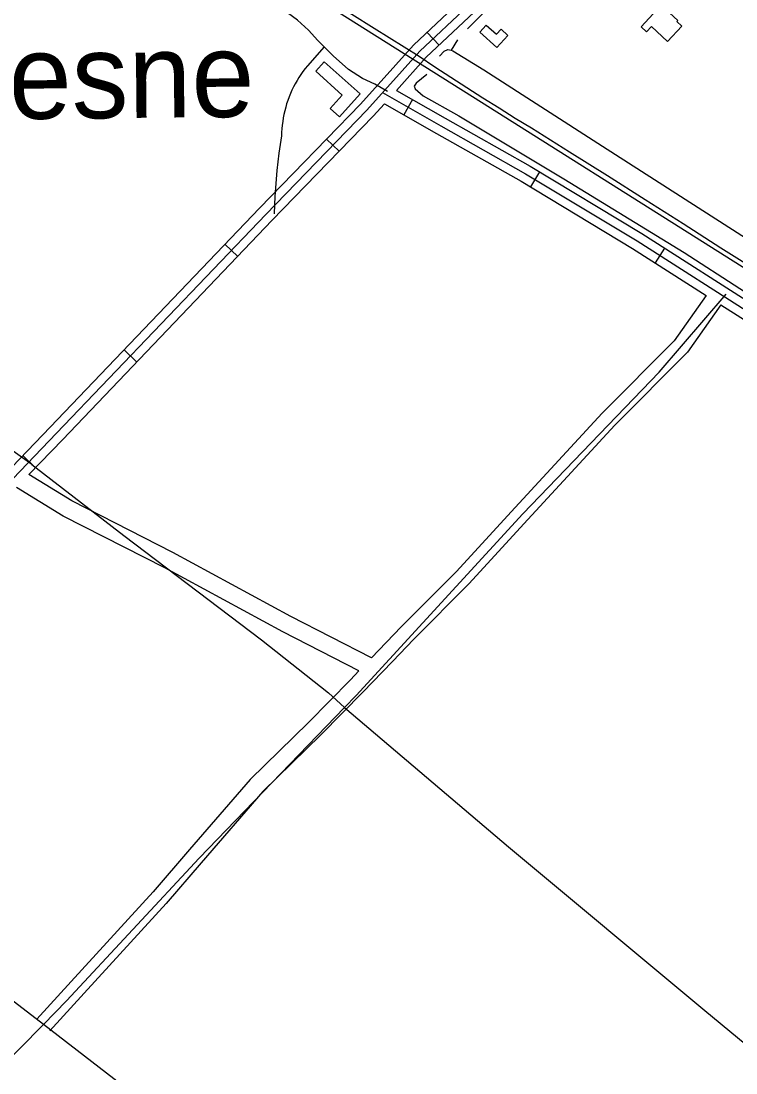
# Model space of a CAD drawing. Extents: x 3567028 to 3605064, y 510945 to 536587.
# Drawn here: x 3578608 to 3579831, y 524024 to 525823 of the extents above; entities that cross this region are included whole.
import ezdxf

# ---------------------------------------------------------------- set-up
doc = ezdxf.new("R2010")
doc.units = 0
for name, color, linetype in [('V-BLDG-OTLN', 7, 'Continuous'), ('V-DTCH-CNTR', 7, 'Continuous'), ('V-RAIL-TRAK', 7, 'Continuous'), ('V-ROAD-CNTR', 7, 'Continuous'), ('V-TOPO-GNAM-IDEN', 7, 'Continuous'), ('V-TOPO-SHOR', 7, 'Continuous')]:
    doc.layers.add(name, color=color, linetype=linetype)

msp = doc.modelspace()

# ---------------------------------------------------------------- linework, layer by layer
at = {"layer": 'V-BLDG-OTLN'}
for points in [[(3579668.3, 525812.8), (3579702.7, 525850.1), (3579731.4, 525823.6), (3579729.7, 525821.7), (3579737.9, 525814.2), (3579713.8, 525788), (3579686.3, 525813.4), (3579677.7, 525804.1)], [(3579440.6, 525798), (3579421.6, 525777.3), (3579392.7, 525803.9), (3579403.6, 525815.9), (3579420.8, 525800.1), (3579428.9, 525808.8)], [(3579126.4, 525752.9), (3579187.6, 525698.1), (3579152.4, 525658.8), (3579136.6, 525673), (3579157.3, 525696.1), (3579111.9, 525736.8)]]:
    msp.add_lwpolyline(points, close=True, dxfattribs=at)
at = {"layer": 'V-DTCH-CNTR'}
for points in [[(3579234.5, 525702), (3579213.1, 525714.8), (3579191.9, 525724.7), (3579167.8, 525740), (3579141.8, 525763), (3579126.3, 525778.7), (3579115.6, 525789.6), (3579099.3, 525807.1), (3579080.9, 525824), (3579063.6, 525836.8), (3578973.6, 525897.7), (3578789, 526012), (3578549.7, 526156)], [(3579126.3, 525778.7), (3579097.6, 525746.3), (3579093.7, 525741.4), (3579090, 525736.4), (3579086.4, 525731.4), (3579083, 525726.2), (3579079.8, 525720.9), (3579076.7, 525715.5), (3579073.8, 525710), (3579071.1, 525704.4), (3579068.6, 525698.7), (3579066.3, 525692.9), (3579064.1, 525687.1), (3579062.1, 525681.2), (3579060.4, 525675.3), (3579058.8, 525669.3), (3579057.4, 525663.2), (3579056.2, 525657.1), (3579055.3, 525651), (3579054.5, 525644.8), (3579053.9, 525638.7), (3579053.5, 525632.5), (3579053.3, 525626.3), (3579051, 525611.6), (3579048.9, 525596.9), (3579047.1, 525582.2), (3579045.4, 525567.4), (3579044, 525552.6), (3579042.9, 525537.8), (3579041.9, 525523), (3579041.2, 525508.2), (3579040.7, 525493.3)], [(3578048.1, 523479.3), (3578209, 523654.8), (3578438, 523896.7), (3578646, 524107.2), (3578685.5, 524147.2), (3578912.7, 524391.6), (3579161.3, 524648.8), (3579181.1, 524669.3), (3579466.2, 524980), (3579699.3, 525222.2), (3579814.1, 525355.8)], [(3578625.9, 525064.3), (3578582.4, 525096.1)], [(3578625.9, 525064.3), (3578783.7, 524943.1), (3579019.1, 524764.4), (3579133.5, 524674), (3579161.3, 524648.8), (3579441.4, 524410.6), (3579777.7, 524130.7), (3579889.4, 524038.8)], [(3579434.7, 523481.5), (3579147.6, 523711), (3578836.6, 523959.9), (3578646, 524107.2), (3578395, 524299.5), (3578155.5, 524480.6), (3578106.4, 524518.4)]]:
    msp.add_lwpolyline(points, dxfattribs=at)
at = {"layer": 'V-RAIL-TRAK'}
msp.add_lwpolyline([(3579885.3, 525384), (3579804.6, 525434.5), (3579740.2, 525475.9), (3579675.6, 525517), (3579610.8, 525558), (3579545.9, 525598.8), (3579480.9, 525639.3), (3579453.2, 525656.3), (3579425.5, 525673.5), (3579397.9, 525690.9), (3579370.4, 525708.4), (3579343, 525726.1), (3579315.8, 525743.9), (3579288.6, 525761.9), (3579211.8, 525809.8), (3579135.2, 525858)], dxfattribs=at)
at = {"layer": 'V-ROAD-CNTR'}
for p, q in [((3579302.3, 525803.3), (3579322.8, 525781.5)), ((3579277.1, 525688.6), (3579262.3, 525662.6)), ((3579130.4, 525621), (3579151.9, 525600)), ((3579494.7, 525564.7), (3579479.2, 525539)), ((3578956.6, 525441.1), (3578978.3, 525420.3)), ((3579708.6, 525434.5), (3579692.4, 525409.2)), ((3578783.9, 525260.4), (3578805.5, 525239.6)), ((3578611, 525079.8), (3578632.6, 525059))]:
    msp.add_line(p, q, dxfattribs=at)
for points in [[(3571107.5, 530923.8), (3571335.7, 530779.9), (3572456, 530074.7), (3572913.2, 529784.9), (3573353.2, 529506.1), (3574011.9, 529090.4), (3574465.9, 528803.8), (3574566.4, 528736.8), (3574909.2, 528519.1), (3575756.4, 527984.9), (3576622.6, 527437), (3577459.5, 526912.7), (3578223.7, 526427.4), (3578886.3, 526005.2), (3579395.2, 525684), (3580151.7, 525207.4), (3580699, 524864.7), (3581176, 524557.8)], [(3574581.1, 520872.4), (3574883.2, 521186.5), (3575196.1, 521512.2), (3575509.3, 521844.1), (3575693.8, 522034.2), (3575994.5, 522352.1), (3576360.4, 522728), (3576744.3, 523129.9), (3577117.9, 523519.4), (3577438.1, 523854.9), (3577799, 524225.1), (3578082.2, 524526.3), (3578344.7, 524802.5), (3578657.4, 525128.2), (3579015.4, 525502.5), (3579188.4, 525680.6), (3579279.3, 525781.7), (3579444.6, 525937.6), (3579516.5, 526007.6)], [(3579527, 525996.8), (3579455, 525926.8), (3579290.1, 525771.2), (3579199.3, 525670.4), (3579026.2, 525492.1), (3578668.3, 525117.8), (3578355.6, 524792.1), (3578093.1, 524516), (3577809.8, 524214.7), (3577448.9, 523844.4), (3577128.7, 523509), (3576755.2, 523119.5), (3576371.2, 522717.6), (3576005.3, 522341.8), (3575704.6, 522023.8), (3575520.1, 521833.7), (3575206.9, 521501.8), (3574894, 521176.1), (3574602.1, 520872.6)], [(3579249.9, 525704.1), (3579300.8, 525760.7), (3579465.4, 525915.9), (3579537.4, 525986.1)], [(3579226.2, 525700.3), (3579326.1, 525643.6), (3579470.8, 525561.6), (3579661.6, 525446.7), (3579868.5, 525314.6), (3580066.5, 525192.7), (3580337.5, 525018.2), (3580502.7, 524913.8), (3580606.8, 524843.7), (3580624.3, 524823.7), (3580632.6, 524791.5), (3580679.5, 524747.4), (3580784.6, 524687.2), (3580878.9, 524624.3), (3580988.7, 524565.7), (3581068.9, 524506.1)], [(3579249.9, 525704.1), (3579333.5, 525656.7), (3579478.4, 525574.6), (3579669.6, 525459.4), (3579876.5, 525327.3), (3580074.5, 525205.4), (3580345.6, 525030.9), (3580510.9, 524926.4), (3580614.7, 524856.5)], [(3578621.3, 525047.2), (3578679.1, 525107.4), (3579037, 525481.7), (3579210.3, 525660.1), (3579229.3, 525681.3)], [(3579229.3, 525681.3), (3579318.7, 525630.6), (3579463.2, 525548.7), (3579653.7, 525433.9), (3579779.5, 525353.6)], [(3579779.5, 525353.6), (3579724.9, 525275.9), (3579601.7, 525152.2), (3579452.8, 524991), (3579352.1, 524881.2), (3579258.2, 524786.7), (3579207.5, 524734)], [(3579804.8, 525337.5), (3579748, 525256.5), (3579623.4, 525131.5), (3579474.8, 524970.7), (3579373.8, 524860.5), (3579279.6, 524765.7), (3579243.2, 524727.9)], [(3579804.8, 525337.5), (3579860.6, 525301.9), (3580058.5, 525180), (3580329.5, 525005.6), (3580494.5, 524901.3), (3580595.6, 524833.1)], [(3579207.5, 524734), (3579069.5, 524804.8), (3578867.5, 524914), (3578694.6, 525002.6), (3578621.3, 525047.2)], [(3579185.8, 524711.4), (3579055.5, 524778.2), (3578853.5, 524887.5), (3578680, 524976.4), (3578600, 525025)], [(3579243.2, 524727.9), (3579208.8, 524692)], [(3579185.8, 524711.4), (3579171.4, 524696.5), (3579099.6, 524623.4), (3578999.7, 524525.7), (3578896, 524405.9)], [(3579208.8, 524692), (3579192.9, 524675.6), (3579120.8, 524602.1), (3579021.6, 524505.1), (3578916.1, 524383.2)], [(3578896, 524405.9), (3578833.8, 524334), (3578693.3, 524180.5), (3578634.7, 524116.2)], [(3578916.1, 524383.2), (3578856.2, 524314), (3578715.5, 524160.3), (3578656.9, 524096)]]:
    msp.add_lwpolyline(points, dxfattribs=at)
at = {"layer": 'V-TOPO-SHOR'}
for p, q in [((3579437.1, 525876.4), (3579371.6, 525809.2)), ((3579354.5, 525790.6), (3579343.3, 525772.7))]:
    msp.add_line(p, q, dxfattribs=at)
for points in [[(3579323.6, 525762.5), (3579331.4, 525771.5), (3579337.8, 525774.2), (3579343.3, 525772.7), (3579346.1, 525771.9), (3579399.3, 525739.5), (3579602.3, 525608.8), (3579877.1, 525432.7), (3580117.4, 525283.8), (3580313.6, 525162.3), (3580502.9, 525047.8), (3580661.3, 524948.3), (3580673.4, 524940.7)], [(3579302.1, 525731.5), (3579283.7, 525716.5), (3579280.1, 525711.6), (3579282.1, 525706.7), (3579295.8, 525694.6), (3579356.7, 525660.7), (3579536.3, 525552.7), (3579742.2, 525426.8), (3579932.7, 525303.9), (3580173, 525152.9), (3580399.5, 525007.1), (3580605.9, 524872.1), (3580614.2, 524872.6), (3580617.1, 524878.2), (3580622.2, 524887.2)]]:
    msp.add_lwpolyline(points, dxfattribs=at)

# ---------------------------------------------------------------- texts
at = {"layer": 'V-TOPO-GNAM-IDEN'}
msp.add_text('Dufresne', height=145, rotation=0.555, dxfattribs=at).set_placement((3578220.8, 525651.5))

doc.saveas('drawing.dxf')
